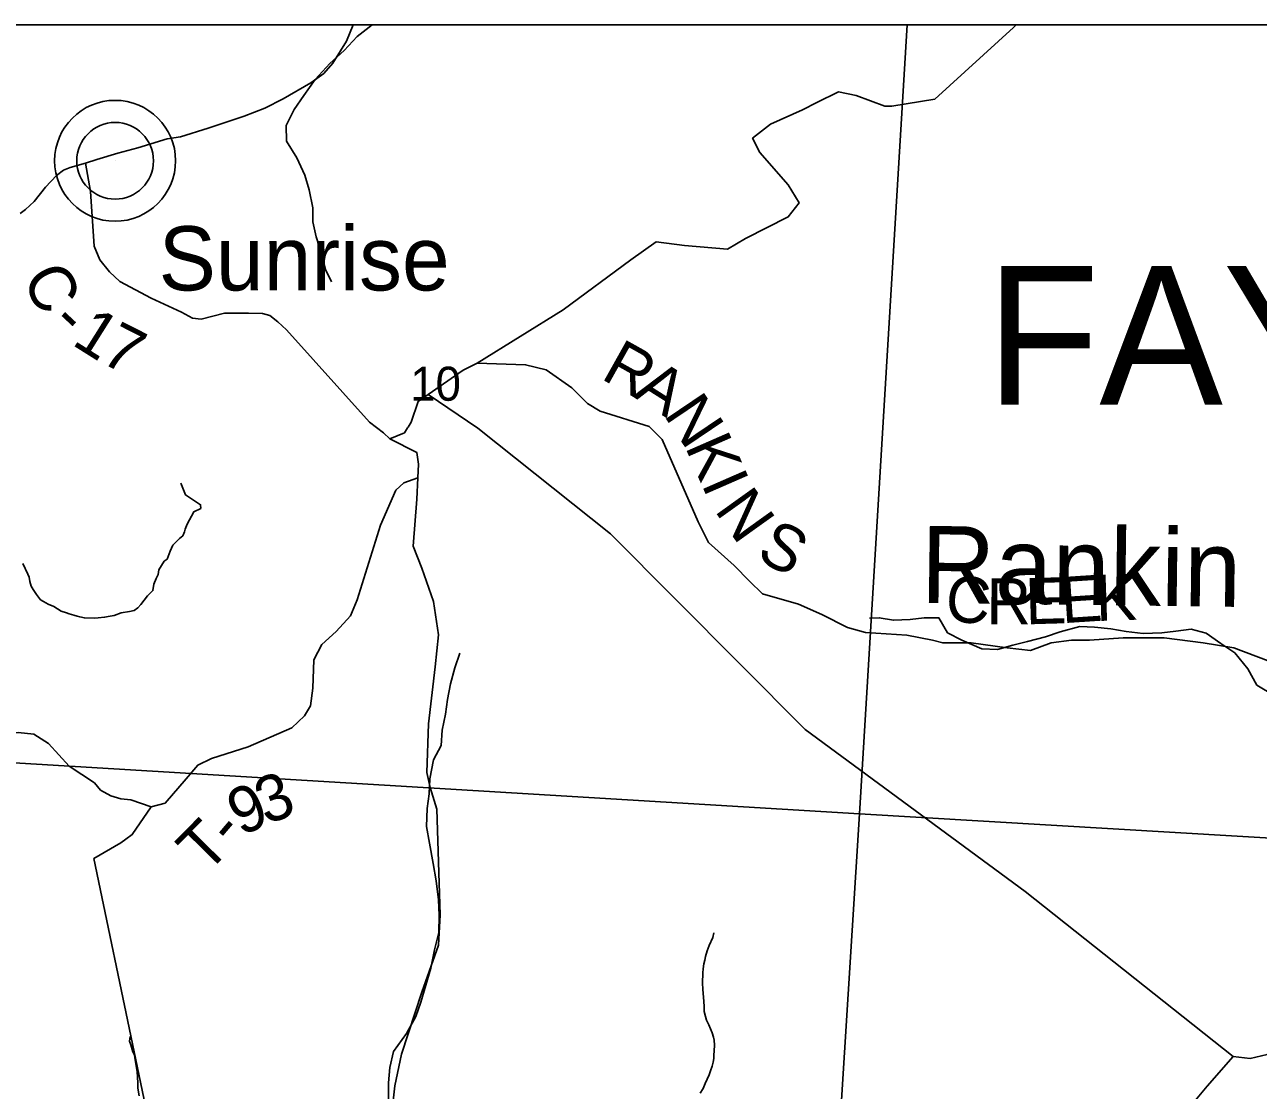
# Model space of a CAD drawing. Extents: x 1949938.81 to 1949945.61, y 152207.65 to 152214.09.
# Drawn here: x 1949942.704 to 1949944.221, y 152212.776 to 152214.087 of the extents above; entities that cross this region are included whole.
import ezdxf

# ---------------------------------------------------------------- set-up
doc = ezdxf.new("R2010")
doc.units = 0
for name, color, linetype in [('GM_X_County', 7, 'Continuous'), ('GM_X_County_Road', 7, 'Continuous'), ('GM_X_County_Road_Text', 7, 'Continuous'), ('GM_X_Minor_River', 7, 'Continuous'), ('GM_X_Minor_River_Text', 7, 'Continuous'), ('GM_X_Section', 7, 'Continuous'), ('GM_X_Section_Text', 7, 'Continuous'), ('GM_X_State_Route', 7, 'Continuous'), ('GM_X_Township', 7, 'Continuous'), ('GM_X_Township_Road', 7, 'Continuous'), ('GM_X_Township_Road_Text', 7, 'Continuous'), ('GM_X_Township_ROW', 7, 'Continuous'), ('GM_X_Township_Text', 7, 'Continuous'), ('GM_X_Unincorporated', 7, 'Continuous'), ('GM_X_Unincorporated_Location', 7, 'Continuous'), ('GM_X_Unincorporated_Text', 7, 'Continuous')]:
    doc.layers.add(name, color=color, linetype=linetype)

msp = doc.modelspace()

# ---------------------------------------------------------------- linework, layer by layer
at = {"layer": 'GM_X_County'}
msp.add_lwpolyline([(1949945.6069, 152208.8266), (1949945.6069, 152214.0874), (1949938.8069, 152214.0874), (1949938.8069, 152213.1813)], dxfattribs=at)
at = {"layer": 'GM_X_County_Road'}
for points in [[(1949942.7785, 152213.9168), (1949942.7847, 152213.8822), (1949942.7891, 152213.8149), (1949942.7964, 152213.7982), (1949942.8083, 152213.7833), (1949942.8207, 152213.7713), (1949942.8596, 152213.7508), (1949942.8969, 152213.7335), (1949942.9104, 152213.7263), (1949942.9208, 152213.725), (1949942.9498, 152213.7324), (1949942.9793, 152213.7324), (1949942.9964, 152213.732), (1949943.0054, 152213.7294), (1949943.0152, 152213.7217), (1949943.0261, 152213.7119), (1949943.1282, 152213.5982), (1949943.1453, 152213.5854), (1949943.1531, 152213.5777), (1949943.1709, 152213.5854), (1949943.1749, 152213.5914), (1949943.1754, 152213.5922)], [(1949943.1754, 152213.5922), (1949943.1794, 152213.5982), (1949943.1879, 152213.6238), (1949943.2001, 152213.6322), (1949943.2434, 152213.6622), (1949943.2605, 152213.6708), (1949943.32, 152213.6689), (1949943.3453, 152213.6626), (1949943.377, 152213.6404), (1949943.396, 152213.6214), (1949943.4119, 152213.6119), (1949943.4721, 152213.5929), (1949943.4879, 152213.5771), (1949943.5323, 152213.4757), (1949943.545, 152213.4504), (1949943.5767, 152213.4219), (1949943.5956, 152213.4028), (1949943.6115, 152213.387), (1949943.6559, 152213.3743), (1949943.6844, 152213.3617), (1949943.7161, 152213.3458), (1949943.7382, 152213.3395), (1949943.7889, 152213.3363), (1949943.8206, 152213.33), (1949943.8333, 152213.3268), (1949943.8682, 152213.3268), (1949943.9125, 152213.3205), (1949943.941, 152213.3173), (1949943.9664, 152213.3268), (1949943.9917, 152213.33), (1949944.0139, 152213.33), (1949944.0551, 152213.3331), (1949944.1058, 152213.3331), (1949944.1534, 152213.3268), (1949944.1914, 152213.3205), (1949944.3181, 152213.2729)], [(1949943.1572, 152212.7632), (1949943.1592, 152212.7817), (1949943.1675, 152212.8209), (1949943.1922, 152212.8972), (1949943.2129, 152212.9549), (1949943.2149, 152212.9921), (1949943.2108, 152213.122), (1949943.2026, 152213.1488), (1949943.1984, 152213.1673), (1949943.2005, 152213.2272), (1949943.2087, 152213.2973), (1949943.2129, 152213.3365), (1949943.2067, 152213.3777), (1949943.1922, 152213.4189), (1949943.1819, 152213.4458), (1949943.1861, 152213.5035), (1949943.1873, 152213.5297), (1949943.1881, 152213.5468), (1949943.1861, 152213.5612), (1949943.1531, 152213.5777)]]:
    msp.add_lwpolyline(points, dxfattribs=at)
at = {"layer": 'GM_X_Minor_River'}
for points in [[(1949943.1312, 152214.0874), (1949943.1311, 152214.0873), (1949943.1129, 152214.073), (1949943.0969, 152214.0556), (1949943.0794, 152214.0397), (1949943.0611, 152214.02), (1949943.0474, 152214.0003), (1949943.0352, 152213.9829), (1949943.0253, 152213.9632), (1949943.026, 152213.9442), (1949943.0388, 152213.9237), (1949943.0485, 152213.9024), (1949943.0537, 152213.8842), (1949943.0582, 152213.8621), (1949943.0581, 152213.8447), (1949943.0626, 152213.8264), (1949943.0693, 152213.8052), (1949943.0738, 152213.7862), (1949943.0813, 152213.771)], [(1949942.7015, 152213.4246), (1949942.7077, 152213.4115), (1949942.7092, 152213.4077), (1949942.7102, 152213.4024), (1949942.7116, 152213.3967), (1949942.7142, 152213.3925), (1949942.7182, 152213.3863), (1949942.7231, 152213.3798), (1949942.7268, 152213.3778), (1949942.7328, 152213.3743), (1949942.7396, 152213.3715), (1949942.7441, 152213.3688), (1949942.7489, 152213.366), (1949942.7553, 152213.3637), (1949942.7587, 152213.3625), (1949942.7644, 152213.3608), (1949942.7682, 152213.3596), (1949942.7715, 152213.3588), (1949942.7772, 152213.3576), (1949942.7893, 152213.3574), (1949942.7943, 152213.3577), (1949942.8022, 152213.3583), (1949942.8091, 152213.3597), (1949942.814, 152213.3604), (1949942.8224, 152213.3637), (1949942.8326, 152213.3654), (1949942.8387, 152213.3668), (1949942.8429, 152213.3698), (1949942.8468, 152213.3739), (1949942.855, 152213.3848), (1949942.8615, 152213.3911), (1949942.8628, 152213.3991), (1949942.8656, 152213.4059), (1949942.8679, 152213.4111), (1949942.8688, 152213.4168), (1949942.8754, 152213.4273), (1949942.8792, 152213.4299), (1949942.8828, 152213.4397), (1949942.886, 152213.4469), (1949942.8941, 152213.4551), (1949942.8983, 152213.4585), (1949942.9003, 152213.4634), (1949942.9011, 152213.4668), (1949942.9039, 152213.4728), (1949942.9121, 152213.4882), (1949942.9205, 152213.4923), (1949942.9202, 152213.4968), (1949942.9015, 152213.5089), (1949942.896, 152213.5234)], [(1949944.2409, 152213.2619), (1949944.2198, 152213.2749), (1949944.2085, 152213.2947), (1949944.1927, 152213.3145), (1949944.1753, 152213.3259), (1949944.1572, 152213.3389), (1949944.139, 152213.3435), (1949944.1201, 152213.3413), (1949944.1027, 152213.3391), (1949944.0799, 152213.3384), (1949944.0587, 152213.3408), (1949944.0398, 152213.3439), (1949944.0201, 152213.3462), (1949944.002, 152213.3471), (1949943.9777, 152213.3403), (1949943.9595, 152213.3343), (1949943.9375, 152213.3283), (1949943.9193, 152213.3238), (1949943.9004, 152213.3186), (1949943.8814, 152213.3194), (1949943.8565, 152213.3301), (1949943.8391, 152213.3393), (1949943.8286, 152213.3576), (1949943.8104, 152213.3576), (1949943.793, 152213.3554), (1949943.7725, 152213.3547), (1949943.7551, 152213.3578), (1949943.743, 152213.3571)], [(1949943.1512, 152212.7413), (1949943.1514, 152212.7853), (1949943.153, 152212.8043), (1949943.1576, 152212.824), (1949943.1736, 152212.846), (1949943.185, 152212.8672), (1949943.1912, 152212.8846), (1949943.2035, 152212.9264), (1949943.2081, 152212.9491), (1949943.2135, 152212.9704), (1949943.2136, 152212.9916), (1949943.2129, 152213.0106), (1949943.21, 152213.0341), (1949943.2063, 152213.0554), (1949943.2018, 152213.0805), (1949943.1981, 152213.101), (1949943.199, 152213.123), (1949943.2013, 152213.1412), (1949943.2022, 152213.1594), (1949943.2068, 152213.1829), (1949943.216, 152213.2004), (1949943.2176, 152213.2193), (1949943.2214, 152213.2391), (1949943.2238, 152213.2573), (1949943.2277, 152213.2762), (1949943.233, 152213.296), (1949943.2392, 152213.3142)], [(1949943.5394, 152212.932), (1949943.5406, 152212.9365), (1949943.5414, 152212.941), (1949943.5434, 152212.9478), (1949943.5458, 152212.9546), (1949943.5505, 152212.9644), (1949943.5514, 152212.9701)], [(1949943.5347, 152212.7729), (1949943.5385, 152212.7786), (1949943.5409, 152212.7846), (1949943.5433, 152212.7899), (1949943.5457, 152212.7955), (1949943.5476, 152212.8004), (1949943.5496, 152212.8061), (1949943.5509, 152212.811), (1949943.5517, 152212.8156), (1949943.5518, 152212.8197), (1949943.5522, 152212.825), (1949943.5524, 152212.8319), (1949943.5521, 152212.8379), (1949943.551, 152212.8418), (1949943.5496, 152212.8471), (1949943.5456, 152212.8567), (1949943.5427, 152212.8628), (1949943.5412, 152212.867), (1949943.5398, 152212.8731), (1949943.5396, 152212.8796), (1949943.5393, 152212.8856), (1949943.538, 152212.9008), (1949943.5378, 152212.9081), (1949943.538, 152212.921), (1949943.5385, 152212.9259), (1949943.5394, 152212.932)], [(1949942.8445, 152212.7694), (1949942.8431, 152212.7789), (1949942.8429, 152212.7854), (1949942.8426, 152212.7926), (1949942.842, 152212.799), (1949942.841, 152212.8063), (1949942.8392, 152212.8162), (1949942.8389, 152212.8196), (1949942.8367, 152212.8238), (1949942.8342, 152212.8322), (1949942.8328, 152212.8368), (1949942.8337, 152212.8425)]]:
    msp.add_lwpolyline(points, dxfattribs=at)
at = {"layer": 'GM_X_Section'}
for p, q in [((1949943.7893, 152214.0874), (1949942.6841, 152214.0874)), ((1949944.5169, 152214.0874), (1949943.7893, 152214.0874))]:
    msp.add_line(p, q, dxfattribs=at)
for points in [[(1949942.6841, 152214.0874), (1949942.623, 152213.1832), (1949943.7308, 152213.1166), (1949943.7893, 152214.0874)], [(1949943.7893, 152214.0874), (1949943.7308, 152213.1166), (1949944.8197, 152213.0519), (1949944.873, 152214.065), (1949944.5169, 152214.0874)]]:
    msp.add_lwpolyline(points, dxfattribs=at)
for points in [[(1949943.7308, 152213.1166), (1949943.6665, 152212.0918), (1949942.5545, 152212.1539), (1949942.623, 152213.1832)], [(1949944.8197, 152213.0519), (1949944.7648, 152212.0263), (1949943.6665, 152212.0918), (1949943.7308, 152213.1166)]]:
    msp.add_lwpolyline(points, close=True, dxfattribs=at)
at = {"layer": 'GM_X_State_Route'}
msp.add_lwpolyline([(1949942.6982, 152213.855), (1949942.7048, 152213.8599), (1949942.7155, 152213.8698), (1949942.7294, 152213.8873), (1949942.743, 152213.902), (1949942.7516, 152213.9085), (1949942.7599, 152213.9117), (1949942.7785, 152213.9168), (1949942.7924, 152213.9215), (1949942.8183, 152213.9292), (1949942.8429, 152213.936), (1949942.8789, 152213.947), (1949942.8955, 152213.9496), (1949942.9297, 152213.9599), (1949942.9737, 152213.975), (1949942.9992, 152213.9845), (1949943.0218, 152213.9963), (1949943.0558, 152214.0157), (1949943.0717, 152214.0275), (1949943.0829, 152214.0402), (1949943.0997, 152214.067), (1949943.108, 152214.0874)], dxfattribs=at)
at = {"layer": 'GM_X_Township'}
msp.add_lwpolyline([(1949945.6069, 152208.8266), (1949945.6069, 152214.0874), (1949942.6839, 152214.0874)], dxfattribs=at)
at = {"layer": 'GM_X_Township_Road'}
for points in [[(1949943.2605, 152213.6708), (1949943.3661, 152213.7365), (1949943.4497, 152213.7981), (1949943.4805, 152213.8201), (1949943.5156, 152213.8157), (1949943.5684, 152213.8113), (1949943.5904, 152213.8245), (1949943.6432, 152213.8508), (1949943.6564, 152213.8684), (1949943.6432, 152213.8904), (1949943.608, 152213.93), (1949943.5992, 152213.9476), (1949943.6212, 152213.9651), (1949943.6608, 152213.9827), (1949943.6784, 152213.9915), (1949943.7048, 152214.0047), (1949943.7267, 152214.0003), (1949943.7619, 152213.9871), (1949943.7707, 152213.9871), (1949943.8235, 152213.9959), (1949943.9203, 152214.0838), (1949943.9236, 152214.0874)], [(1949942.8283, 152213.0853), (1949942.8361, 152213.091), (1949942.8594, 152213.1251), (1949942.8766, 152213.1297), (1949942.9024, 152213.1597), (1949942.9168, 152213.1764), (1949942.9338, 152213.1847), (1949942.9789, 152213.1987), (1949943.0323, 152213.2223), (1949943.0482, 152213.2371), (1949943.0554, 152213.2492), (1949943.0581, 152213.2712), (1949943.0596, 152213.3058), (1949943.0695, 152213.3247), (1949943.0869, 152213.3407), (1949943.1047, 152213.36), (1949943.1127, 152213.3797), (1949943.1415, 152213.4716), (1949943.1604, 152213.5145), (1949943.1703, 152213.5239), (1949943.1873, 152213.5297)], [(1949942.6293, 152213.2371), (1949942.6294, 152213.2371), (1949942.6547, 152213.2239), (1949942.6774, 152213.2163), (1949942.696, 152213.2167), (1949942.7149, 152213.2144), (1949942.7331, 152213.203), (1949942.7585, 152213.1753), (1949942.7895, 152213.1544), (1949942.7971, 152213.1457), (1949942.8096, 152213.1385), (1949942.8221, 152213.135), (1949942.8346, 152213.1335), (1949942.8594, 152213.1251)], [(1949944.136, 152212.7543), (1949944.1587, 152212.7815), (1949944.1905, 152212.8179)]]:
    msp.add_lwpolyline(points, dxfattribs=at)
at = {"layer": 'GM_X_Township_ROW'}
for points in [[(1949944.1905, 152212.8179), (1949943.9347, 152213.0211), (1949943.6639, 152213.2201), (1949943.4245, 152213.4609), (1949943.2614, 152213.591), (1949943.2001, 152213.6322)], [(1949942.8879, 152212.5297), (1949942.886, 152212.5528), (1949942.8883, 152212.5858), (1949942.789, 152213.0614), (1949942.8221, 152213.0808), (1949942.8283, 152213.0853)], [(1949944.1905, 152212.8179), (1949944.2114, 152212.8155), (1949944.2323, 152212.8203), (1949944.2612, 152212.828), (1949944.3009, 152212.8376), (1949944.3412, 152212.8652), (1949944.3713, 152212.8736), (1949944.3994, 152212.8639), (1949944.463, 152212.8223), (1949944.4973, 152212.7917), (1949944.5162, 152212.779), (1949944.5333, 152212.7731)]]:
    msp.add_lwpolyline(points, dxfattribs=at)
at = {"layer": 'GM_X_Unincorporated'}
for radius in [0.0744, 0.0472]:
    msp.add_circle((1949942.8151, 152213.9199), radius, dxfattribs=at)
at = {"layer": 'GM_X_Unincorporated_Location'}
msp.add_line((1949942.8151, 152213.9199), (1949942.8151, 152213.9199), dxfattribs=at)

# ---------------------------------------------------------------- texts
at = {"layer": 'GM_X_County_Road_Text'}
for s, rotation, p in [('C', 298.2217, (1949942.6995, 152213.7748)), ('-', 316.97, (1949942.7339, 152213.7177)), ('1', 327.8251, (1949942.7603, 152213.6946)), ('7', 333.1217, (1949942.7949, 152213.6731)), ('R', 330.78, (1949943.4112, 152213.6525)), ('A', 327.6869, (1949943.4512, 152213.6301)), ('N', 304.025, (1949943.489, 152213.6077)), ('K', 293.6398, (1949943.5157, 152213.5686)), ('I', 293.5955, (1949943.5358, 152213.5228)), ('N', 305.5773, (1949943.5515, 152213.4902)), ('S', 332.127, (1949943.602, 152213.4308)), ('K', 1.9164, (1949944.0221, 152213.3536)), ('C', 354.6277, (1949943.8348, 152213.3542)), ('R', 359.9039, (1949943.8869, 152213.3496)), ('E', 1.6911, (1949943.9355, 152213.3495)), ('E', 3.7194, (1949943.9802, 152213.3509))]:
    msp.add_text(s, height=0.0568, rotation=rotation, dxfattribs=at).set_placement(p)
at = {"layer": 'GM_X_Minor_River_Text'}
msp.add_text('Rankin', height=0.09469, rotation=359.2425, dxfattribs=at).set_placement((1949943.8057, 152213.3762))
at = {"layer": 'GM_X_Section_Text'}
msp.add_text('10', height=0.04186, rotation=0, dxfattribs=at).set_placement((1949943.1782, 152213.6247))
at = {"layer": 'GM_X_Township_Road_Text'}
for s, rotation, p in [('3', 21.212, (1949943.001, 152213.1025)), ('9', 24.0758, (1949942.9697, 152213.0885)), ('T', 45.45, (1949942.9271, 152213.0411)), ('-', 49.6189, (1949942.9599, 152213.0747))]:
    msp.add_text(s, height=0.0568, rotation=rotation, dxfattribs=at).set_placement(p)
at = {"layer": 'GM_X_Township_Text'}
msp.add_text('FAYETTE', height=0.17045, rotation=0, dxfattribs=at).set_placement((1949943.8866, 152213.62))
at = {"layer": 'GM_X_Unincorporated_Text'}
msp.add_text('Sunrise', height=0.07898, rotation=0, dxfattribs=at).set_placement((1949942.8686, 152213.7604))

doc.saveas('drawing.dxf')
